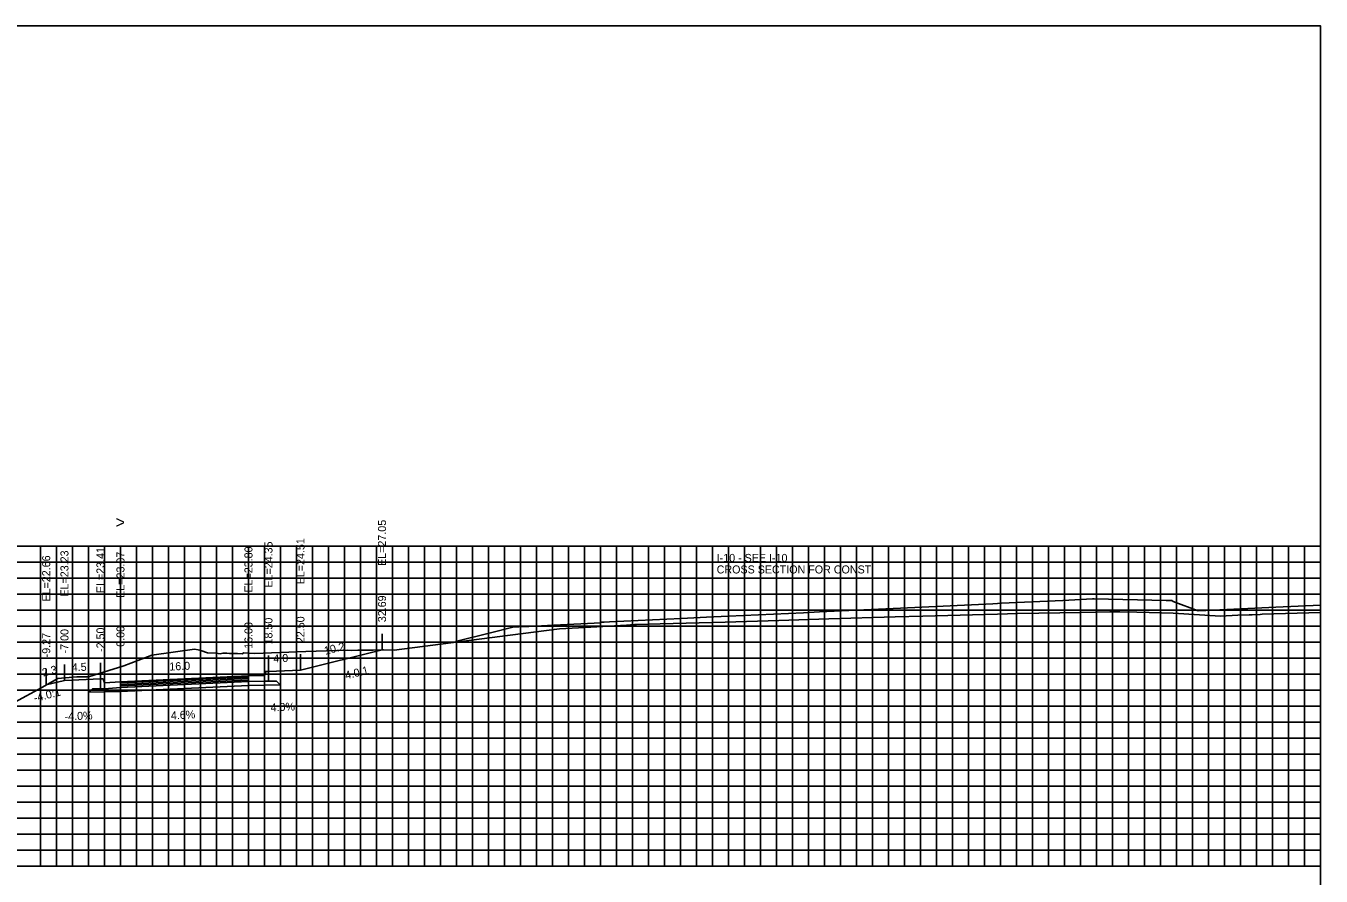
# Model space of a CAD drawing. Extents: x 1797652 to 1804159, y 242516 to 246906.
# Drawn here: x 1803312.7 to 1803474.5, y 242599.8 to 242706 of the extents above; entities that cross this region are included whole.
import ezdxf

# ---------------------------------------------------------------- set-up
doc = ezdxf.new("R2010")
doc.units = 0
for name, color, linetype in [('2', 7, 'Continuous'), ('3', 7, 'Continuous'), ('4', 7, 'Continuous'), ('60', 7, 'Continuous'), ('BASE', 7, 'Continuous'), ('CL-CNST', 7, 'Continuous'), ('Level 62', 7, 'Continuous'), ('LOWER BINDER', 7, 'Continuous'), ('M-ROADS', 7, 'Continuous'), ('UPPER BINDER', 7, 'Continuous')]:
    doc.layers.add(name, color=color, linetype=linetype)

msp = doc.modelspace()

# ---------------------------------------------------------------- linework, layer by layer
for p, q in [((1803357.18, 242628.05), (1803357.18, 242630.05)), ((1803317.49, 242624.23), (1803317.49, 242626.23)), ((1803321.99, 242624.41), (1803321.99, 242626.41)), ((1803340.49, 242624.8), (1803340.49, 242626.8)), ((1803342.99, 242625.35), (1803342.99, 242627.35)), ((1803346.99, 242625.51), (1803346.99, 242627.51)), ((1803315.21, 242623.66), (1803315.21, 242625.66)), ((1803324.49, 242624.07), (1803324.49, 242626.07))]:
    msp.add_line(p, q)
for points in [[(1803174.49, 242516), (1803474.49, 242516), (1803474.49, 242706), (1803174.49, 242706)], [(1803340.49, 242624.8), (1803342.49, 242624.85), (1803342.66, 242625.35), (1803342.99, 242625.35), (1803342.99, 242624.13), (1803342.49, 242624.13), (1803340.49, 242624.08)], [(1803324.49, 242624.07), (1803322.49, 242623.91), (1803322.32, 242624.41), (1803321.99, 242624.41), (1803321.98, 242623.19), (1803322.48, 242623.19), (1803324.49, 242623.35)]]:
    msp.add_lwpolyline(points, close=True)
at = {"layer": '2'}
msp.add_lwpolyline([(1803340.49, 242624.65), (1803340.49, 242624.8), (1803324.49, 242624.07), (1803324.49, 242623.92)], close=True, dxfattribs=at)
at = {"layer": '60'}
for p, q in [((1803474.49, 242601), (1803474.49, 242641)), ((1803474.55, 242641), (1803474.49, 242641)), ((1803474.55, 242631), (1803474.49, 242631)), ((1803474.55, 242621), (1803474.49, 242621)), ((1803474.55, 242611), (1803474.49, 242611)), ((1803174.49, 242601), (1803474.49, 242601)), ((1803314.49, 242600.94), (1803314.49, 242601)), ((1803324.49, 242600.94), (1803324.49, 242601)), ((1803334.49, 242600.94), (1803334.49, 242601)), ((1803344.49, 242600.94), (1803344.49, 242601)), ((1803354.49, 242600.94), (1803354.49, 242601)), ((1803364.49, 242600.94), (1803364.49, 242601)), ((1803374.49, 242600.94), (1803374.49, 242601)), ((1803384.49, 242600.94), (1803384.49, 242601)), ((1803394.49, 242600.94), (1803394.49, 242601)), ((1803404.49, 242600.94), (1803404.49, 242601)), ((1803414.49, 242600.94), (1803414.49, 242601)), ((1803424.49, 242600.94), (1803424.49, 242601)), ((1803434.49, 242600.94), (1803434.49, 242601)), ((1803444.49, 242600.94), (1803444.49, 242601)), ((1803454.49, 242600.94), (1803454.49, 242601)), ((1803464.49, 242600.94), (1803464.49, 242601)), ((1803474.49, 242600.94), (1803474.49, 242601)), ((1803474.55, 242601), (1803474.49, 242601))]:
    msp.add_line(p, q, dxfattribs=at)
at = {"layer": 'BASE'}
msp.add_lwpolyline([(1803324.49, 242623.35), (1803340.49, 242624.08), (1803342.49, 242624.13), (1803342.99, 242624.13), (1803343.99, 242624.15), (1803344.47, 242623.67), (1803340.49, 242623.58), (1803324.49, 242622.85), (1803320.58, 242622.76), (1803320.98, 242623.16), (1803321.98, 242623.19), (1803322.48, 242623.19)], close=True, dxfattribs=at)
at = {"layer": 'CL-CNST'}
for points in [[(1803366.36, 242629.1), (1803370.9, 242630.23), (1803373.51, 242630.88), (1803374.26, 242630.92), (1803375.53, 242630.98), (1803378.67, 242631.13), (1803384.53, 242631.41), (1803384.59, 242631.46), (1803384.61, 242631.49), (1803384.93, 242631.5), (1803385.62, 242631.53), (1803394.57, 242631.96), (1803397.74, 242632.11), (1803400.5, 242632.24), (1803409.85, 242632.68), (1803411.86, 242632.78), (1803421.97, 242633.26), (1803433.51, 242633.81), (1803434.09, 242633.84), (1803434.59, 242633.86), (1803442.27, 242634.23), (1803445.96, 242634.4), (1803446.2, 242634.41), (1803455.19, 242634.21), (1803455.89, 242634.2), (1803456.08, 242634.1), (1803459.19, 242632.9), (1803460.16, 242632.95), (1803468.89, 242633.36), (1803474.49, 242633.63)], [(1803315.21, 242623.66), (1803317.49, 242624.23), (1803321.99, 242624.41), (1803322.32, 242624.41), (1803322.49, 242623.91), (1803324.49, 242624.07), (1803340.49, 242624.8), (1803342.49, 242624.85), (1803342.66, 242625.35), (1803342.99, 242625.35), (1803346.99, 242625.51), (1803357.18, 242628.05)]]:
    msp.add_lwpolyline(points, dxfattribs=at)
at = {"layer": 'Level 62'}
for p, q in [((1803174.49, 242641), (1803474.49, 242641)), ((1803314.49, 242601), (1803314.49, 242641)), ((1803316.49, 242601), (1803316.49, 242641)), ((1803318.49, 242601), (1803318.49, 242641)), ((1803320.49, 242601), (1803320.49, 242641)), ((1803322.49, 242601), (1803322.49, 242641)), ((1803324.49, 242601), (1803324.49, 242641)), ((1803326.49, 242601), (1803326.49, 242641)), ((1803328.49, 242601), (1803328.49, 242641)), ((1803330.49, 242601), (1803330.49, 242641)), ((1803332.49, 242601), (1803332.49, 242641)), ((1803334.49, 242601), (1803334.49, 242641)), ((1803336.49, 242601), (1803336.49, 242641)), ((1803338.49, 242601), (1803338.49, 242641)), ((1803340.49, 242601), (1803340.49, 242641)), ((1803342.49, 242601), (1803342.49, 242641)), ((1803344.49, 242601), (1803344.49, 242641)), ((1803346.49, 242601), (1803346.49, 242641)), ((1803348.49, 242601), (1803348.49, 242641)), ((1803350.49, 242601), (1803350.49, 242641)), ((1803352.49, 242601), (1803352.49, 242641)), ((1803354.49, 242601), (1803354.49, 242641)), ((1803356.49, 242601), (1803356.49, 242641)), ((1803358.49, 242601), (1803358.49, 242641)), ((1803360.49, 242601), (1803360.49, 242641)), ((1803362.49, 242601), (1803362.49, 242641)), ((1803364.49, 242601), (1803364.49, 242641)), ((1803366.49, 242601), (1803366.49, 242641)), ((1803368.49, 242601), (1803368.49, 242641)), ((1803370.49, 242601), (1803370.49, 242641)), ((1803372.49, 242601), (1803372.49, 242641)), ((1803374.49, 242601), (1803374.49, 242641)), ((1803376.49, 242601), (1803376.49, 242641)), ((1803378.49, 242601), (1803378.49, 242641)), ((1803380.49, 242601), (1803380.49, 242641)), ((1803382.49, 242601), (1803382.49, 242641)), ((1803384.49, 242601), (1803384.49, 242641)), ((1803386.49, 242601), (1803386.49, 242641)), ((1803388.49, 242601), (1803388.49, 242641)), ((1803390.49, 242601), (1803390.49, 242641)), ((1803392.49, 242601), (1803392.49, 242641)), ((1803394.49, 242601), (1803394.49, 242641)), ((1803396.49, 242601), (1803396.49, 242641)), ((1803398.49, 242601), (1803398.49, 242641)), ((1803400.49, 242601), (1803400.49, 242641)), ((1803402.49, 242601), (1803402.49, 242641)), ((1803404.49, 242601), (1803404.49, 242641)), ((1803406.49, 242601), (1803406.49, 242641)), ((1803408.49, 242601), (1803408.49, 242641)), ((1803410.49, 242601), (1803410.49, 242641)), ((1803412.49, 242601), (1803412.49, 242641)), ((1803414.49, 242601), (1803414.49, 242641)), ((1803416.49, 242601), (1803416.49, 242641)), ((1803418.49, 242601), (1803418.49, 242641)), ((1803420.49, 242601), (1803420.49, 242641)), ((1803422.49, 242601), (1803422.49, 242641)), ((1803424.49, 242601), (1803424.49, 242641)), ((1803426.49, 242601), (1803426.49, 242641)), ((1803428.49, 242601), (1803428.49, 242641)), ((1803430.49, 242601), (1803430.49, 242641)), ((1803432.49, 242601), (1803432.49, 242641)), ((1803434.49, 242601), (1803434.49, 242641)), ((1803436.49, 242601), (1803436.49, 242641)), ((1803438.49, 242601), (1803438.49, 242641)), ((1803440.49, 242601), (1803440.49, 242641)), ((1803442.49, 242601), (1803442.49, 242641)), ((1803444.49, 242601), (1803444.49, 242641)), ((1803446.49, 242601), (1803446.49, 242641)), ((1803448.49, 242601), (1803448.49, 242641)), ((1803450.49, 242601), (1803450.49, 242641)), ((1803452.49, 242601), (1803452.49, 242641)), ((1803454.49, 242601), (1803454.49, 242641)), ((1803456.49, 242601), (1803456.49, 242641)), ((1803458.49, 242601), (1803458.49, 242641)), ((1803460.49, 242601), (1803460.49, 242641)), ((1803462.49, 242601), (1803462.49, 242641)), ((1803464.49, 242601), (1803464.49, 242641)), ((1803466.49, 242601), (1803466.49, 242641)), ((1803468.49, 242601), (1803468.49, 242641)), ((1803470.49, 242601), (1803470.49, 242641)), ((1803472.49, 242601), (1803472.49, 242641)), ((1803474.49, 242601), (1803474.49, 242641)), ((1803174.49, 242639), (1803474.49, 242639)), ((1803174.49, 242637), (1803474.49, 242637)), ((1803174.49, 242635), (1803474.49, 242635)), ((1803174.49, 242633), (1803474.49, 242633)), ((1803174.49, 242631), (1803474.49, 242631)), ((1803174.49, 242629), (1803474.49, 242629)), ((1803174.49, 242627), (1803474.49, 242627)), ((1803174.49, 242625), (1803474.49, 242625)), ((1803174.49, 242623), (1803474.49, 242623)), ((1803174.49, 242621), (1803474.49, 242621)), ((1803174.49, 242619), (1803474.49, 242619)), ((1803174.49, 242617), (1803474.49, 242617)), ((1803174.49, 242615), (1803474.49, 242615)), ((1803174.49, 242613), (1803474.49, 242613)), ((1803174.49, 242611), (1803474.49, 242611)), ((1803174.49, 242609), (1803474.49, 242609)), ((1803174.49, 242607), (1803474.49, 242607)), ((1803174.49, 242605), (1803474.49, 242605)), ((1803174.49, 242603), (1803474.49, 242603)), ((1803174.49, 242601), (1803474.49, 242601))]:
    msp.add_line(p, q, dxfattribs=at)
at = {"layer": 'LOWER BINDER'}
for points in [[(1803324.49, 242623.54), (1803324.49, 242623.73), (1803340.49, 242624.46), (1803340.49, 242624.27)], [(1803324.49, 242623.35), (1803324.49, 242623.54), (1803340.49, 242624.27), (1803340.49, 242624.08)]]:
    msp.add_lwpolyline(points, close=True, dxfattribs=at)
at = {"layer": 'M-ROADS'}
msp.add_lwpolyline([(1803307.86, 242619.66), (1803314.68, 242623.36), (1803316.67, 242624.48), (1803319.04, 242624.66), (1803320.02, 242624.66), (1803320.48, 242624.66), (1803324.9, 242626.04), (1803328.4, 242627.4), (1803333.73, 242628.14), (1803334.2, 242628.05), (1803334.52, 242627.95), (1803335.35, 242627.69), (1803336.45, 242627.62), (1803336.7, 242627.6), (1803336.96, 242627.56), (1803337.29, 242627.65), (1803337.8, 242627.64), (1803338.13, 242627.6), (1803338.42, 242627.58), (1803338.87, 242627.61), (1803339.11, 242627.57), (1803339.71, 242627.56), (1803339.92, 242627.66), (1803340.54, 242627.62), (1803341.23, 242627.59), (1803347.64, 242627.82), (1803352.81, 242628), (1803353.4, 242627.97), (1803354.14, 242627.99), (1803354.73, 242628), (1803355.21, 242627.99), (1803355.94, 242628.02), (1803356.01, 242628.02), (1803356.08, 242628.02), (1803357.14, 242628.05), (1803357.3, 242628.06), (1803357.36, 242628.06), (1803358.72, 242628), (1803373.18, 242629.86), (1803379.38, 242630.66), (1803382.51, 242630.84), (1803387.73, 242631.15), (1803388.72, 242631.21), (1803388.99, 242631.22), (1803391.93, 242631.3), (1803400.06, 242631.5), (1803406.76, 242631.71), (1803413.02, 242631.92), (1803421.3, 242632.15), (1803424.78, 242632.25), (1803434.11, 242632.5), (1803436.61, 242632.57), (1803444.58, 242632.73), (1803448.13, 242632.81), (1803448.63, 242632.81), (1803449.39, 242632.81), (1803451.54, 242632.76), (1803454.61, 242632.69), (1803456.08, 242632.61), (1803461.98, 242632.27), (1803464.13, 242632.36), (1803465.54, 242632.41), (1803465.92, 242632.42), (1803466.95, 242632.48), (1803467.18, 242632.49), (1803474.49, 242632.71)], dxfattribs=at)
at = {"layer": 'UPPER BINDER'}
msp.add_lwpolyline([(1803340.49, 242624.46), (1803340.49, 242624.65), (1803324.49, 242623.92), (1803324.49, 242623.73)], close=True, dxfattribs=at)

# ---------------------------------------------------------------- texts
for s, p in [('4.0:1', (1803352.69, 242624.35)), ('-4.0:1', (1803313.78, 242621.52))]:
    msp.add_text(s, height=1, rotation=14.0362).set_placement(p)
at = {"layer": '3'}
for s, p in [('EL=27.05', (1803357.68, 242638.53)), ('EL=23.41', (1803322.49, 242635.13)), ('EL=23.80', (1803340.99, 242635.2)), ('EL=24.35', (1803343.49, 242635.82)), ('EL=24.51', (1803347.49, 242636.23)), ('EL=22.66', (1803315.71, 242634.08)), ('EL=23.23', (1803317.99, 242634.7)), ('EL=23.07', (1803324.99, 242634.54)), ('32.69', (1803357.68, 242631.5)), ('0.00', (1803324.99, 242628.43)), ('16.00', (1803340.99, 242628.17)), ('18.50', (1803343.49, 242628.72)), ('22.50', (1803347.49, 242628.88)), ('-9.27', (1803315.71, 242627.11)), ('-7.00', (1803317.99, 242627.6)), ('-2.50', (1803322.49, 242627.78))]:
    msp.add_text(s, height=1, rotation=90, dxfattribs=at).set_placement(p)
for s, p in [('I-10 - SEE I-10', (1803399.01, 242639.03)), ('CROSS SECTION FOR CONST ', (1803399.01, 242637.59))]:
    msp.add_text(s, height=1, dxfattribs=at).set_placement(p)
at = {"layer": '4'}
for s, rotation, p in [('10.2', 14.0362, (1803350.09, 242627.42)), ('4.5', 2.2906, (1803318.42, 242625.36)), ('16.0', 2.6337, (1803330.62, 242625.45)), ('4.0', 2.2906, (1803343.62, 242626.47)), ('2.3', 14.0362, (1803314.84, 242624.7)), ('4.0%', 2.2906, (1803343.27, 242620.35)), ('-4.0%', 2.2906, (1803317.53, 242619.22)), ('4.6%', 2.6337, (1803330.81, 242619.35))]:
    msp.add_text(s, height=1, rotation=rotation, dxfattribs=at).set_placement(p)
at = {"layer": '60'}
msp.add_text('>', height=1.5, dxfattribs=at).set_placement((1803323.88, 242643.25))

doc.saveas('drawing.dxf')
